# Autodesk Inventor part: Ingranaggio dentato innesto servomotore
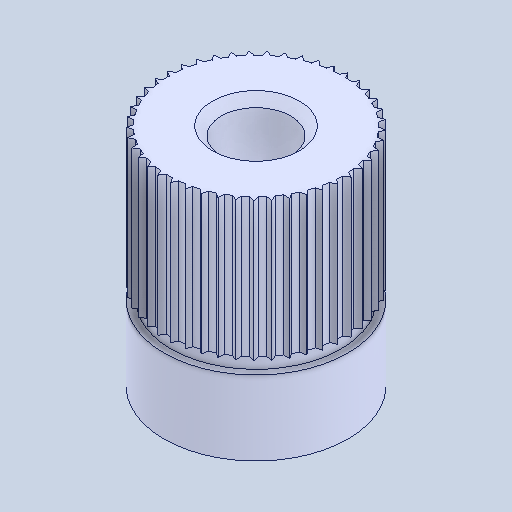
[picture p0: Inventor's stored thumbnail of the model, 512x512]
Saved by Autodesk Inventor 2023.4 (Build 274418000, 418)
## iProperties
Created: 2023-11
Part Number: Ingranaggio dentato innesto servomotore
Material: Générique
Document SubType Name: Modeling
Designer: mel
Density: 1 g/cm^3
Appearance: Par défaut
Author: mel
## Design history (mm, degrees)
feature "Base1"
node "Solide1"
